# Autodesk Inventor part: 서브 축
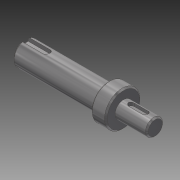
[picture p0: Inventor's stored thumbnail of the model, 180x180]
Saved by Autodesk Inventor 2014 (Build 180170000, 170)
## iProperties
Created: 2016-04
Part Number: 서브 축
Document SubType Name: Modeling
Designer: mdu
Density: 1 g/cm^3
Mass: 19.9624 g
Surface Area: 57.7178 cm^2
Volume: 19.9624 cm^3
Material: 강철, 연강
Appearance: 반광택
Author: mdu
Revision Number: 1
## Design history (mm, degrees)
sketch "스케치1"
  geometry: L1 (-16.331, 0)-(-108.831, 0); L2 (-16.331, 0)-(-16.331, -6); L3 (-16.331, -6)-(-38.831, -6); L4 (-38.831, -12)-(-46.5, -12); L5 (-46.5, -8.5)-(-108.831, -8.5); L6 (-108.831, -8.5)-(-108.831, 0); L7 (-46.5, -8.5)-(-46.5, -12); L8 (-38.831, -6)-(-38.831, -12); L9 (-46.5, 12.249)-(-46.5, -12.249) reference; L10 (-38.831, -17)-(-38.831, 17) reference; 2 further points
  constraints: 17 end point, 4 perpendicular, 2 collinear, 2 parallel, 1 horizontal, 1 midpoint, 1 point on line
  dimensions: "d1" = 12 diameter of L3 L1; "d2" = 24 diameter of L4 L1; "d3" = 17 diameter of L5 L1; "d18" = 22.5 distance of L2.end L3.end; "d20" = 70 distance between parallel lines of L6 L8; "d21" = 7.66872 distance of L4.start L4.end (derived)
revolve "회전1" sketch "스케치1" stored, may be unused: angle "d5" = 90 deg
feature "면 이동1"
chamfer "모따기1" distance "d6" = 0.5; stored, may be unused: second distance "d7" = 2, angle "d8" = 45 deg
node "작업 평면1"
sketch "스케치2"
  geometry: L1 (11.25, 5.5)-(11.25, -5.5) reference; L2 (-5.75, -2)-(4.25, -2); L3 (4.25, 2)-(-5.75, 2); A1 r 2 centre (4.25, 0) between (4.25, -2) and (4.25, 2); A2 r 2 centre (-5.75, 0) between (-5.75, 2) and (-5.75, -2); 2 further points
  constraints: 4 end point, 4 point on circle, 4 tangent, 2 centre point, 1 horizontal alignment, 1 midpoint, 1 parallel, 1 perpendicular
  dimensions: "d9" = 4 distance between parallel lines of L2 L3; "d10" = 14 dimension on A1 A2; "d11" = 5 distance edge to line of A1 L1
extrude "돌출1" cut sketch "스케치2" distance "d12" = 2.5; taper "d13" = 0 deg
node "작업 평면2"
sketch "스케치3"
  geometry: L1 (-31.166, -8)-(-31.166, 8) reference; L2 (-31.166, 2.5)-(-15.666, 2.5); L3 (-15.666, -2.5)-(-31.166, -2.5); A1 r 2.5 centre (-15.666, 0) between (-15.666, -2.5) and (-15.666, 2.5); 2 further points
  constraints: 4 end point, 2 perpendicular, 2 point on circle, 2 point on line, 2 tangent, 1 centre point, 1 horizontal alignment, 1 midpoint
  dimensions: "d14" = 5 distance between parallel lines of L3 L2; "d15" = 18 dimension on A1 L1
extrude "돌출2" cut sketch "스케치3" distance "d16" = 3; taper "d17" = 0 deg
node "솔리드1"
node "참조4"
node "참조5"
